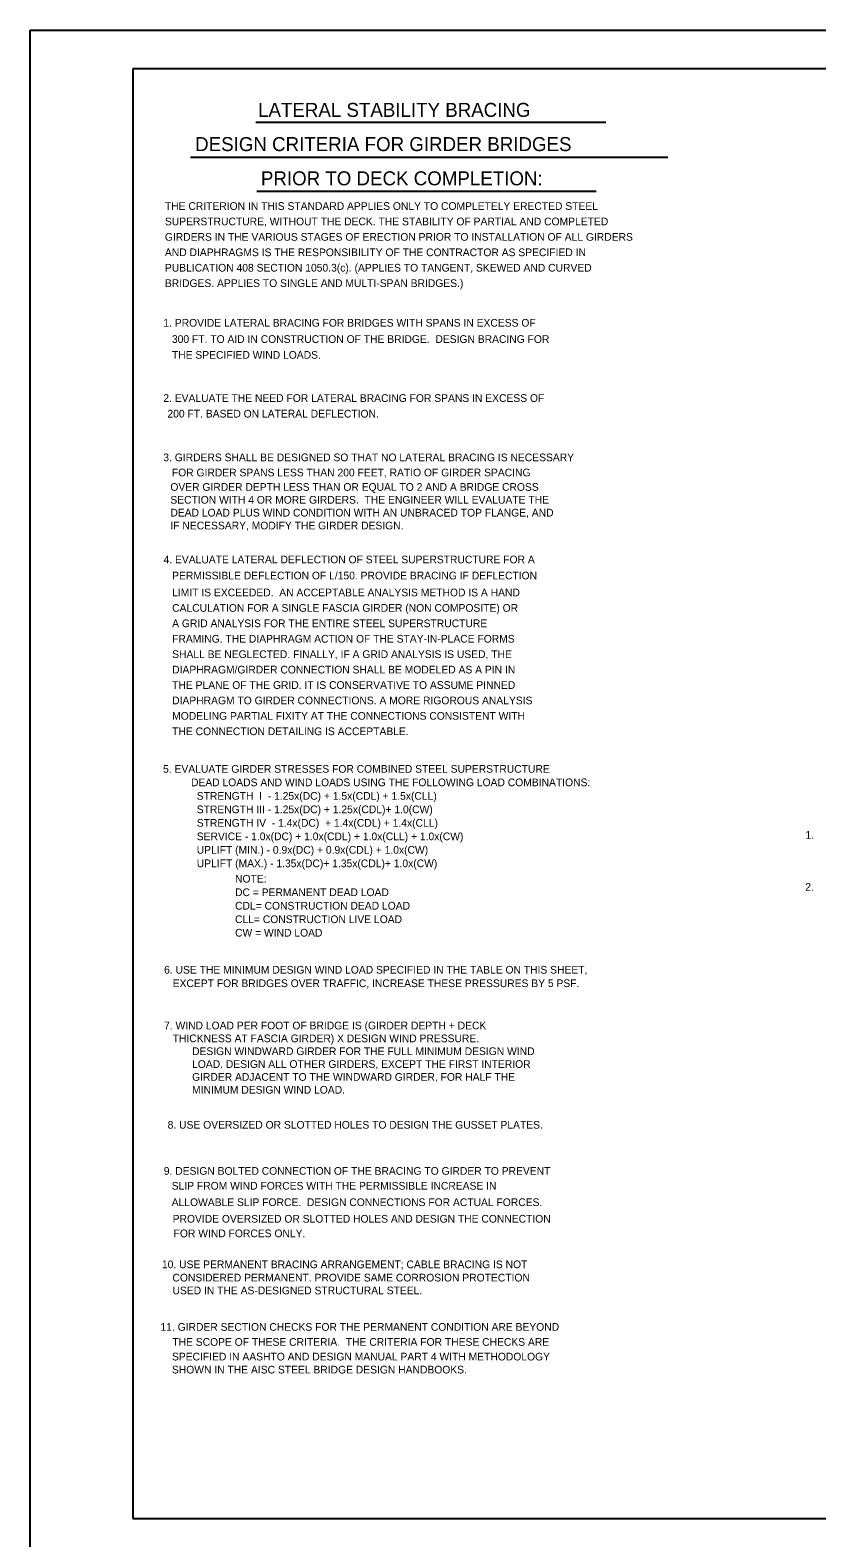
# Model space of a CAD drawing. Extents: x 30 to 2621, y -33 to 1155.
# Drawn here: x 30 to 337, y 568 to 1155 of the extents above; entities that cross this region are included whole.
import ezdxf

# ---------------------------------------------------------------- set-up
doc = ezdxf.new("R2010")
doc.units = 0
doc.layers.add('1', color=7, linetype='Continuous')
doc.layers.add('PLT-BNDY', color=7, linetype='Continuous')

msp = doc.modelspace()

# ---------------------------------------------------------------- linework, layer by layer
at = {"layer": '1'}
for p, q in [((856.5, 1140), (70.5, 1140)), ((70.5, 1140), (70.5, 576)), ((118.31, 1119.17), (254.54, 1119.17)), ((92.84, 1105.65), (278.69, 1105.65)), ((118.75, 1092.35), (250.78, 1092.35)), ((70.5, 576), (856.5, 576))]:
    msp.add_line(p, q, dxfattribs=at)
at = {"layer": 'PLT-BNDY'}
msp.add_lwpolyline([(30.5, 1155), (871.5, 1155), (871.5, 561), (30.5, 561)], close=True, dxfattribs=at)

# ---------------------------------------------------------------- texts
at = {"layer": '1'}
for s, height, p in [('LATERAL STABILITY BRACING', 5.445, (119.19, 1121.26)), ('DESIGN CRITERIA FOR GIRDER BRIDGES', 5.445, (94.71, 1107.95)), ('PRIOR TO DECK COMPLETION:', 5.445, (120.3, 1094.64)), ('THE CRITERION IN THIS STANDARD APPLIES ONLY TO COMPLETELY ERECTED STEEL', 3, (82.94, 1085.08)), ('SUPERSTRUCTURE, WITHOUT THE DECK. THE STABILITY OF PARTIAL AND COMPLETED', 3, (82.94, 1079.08)), ('GIRDERS IN THE VARIOUS STAGES OF ERECTION PRIOR TO INSTALLATION OF ALL GIRDERS', 3, (82.94, 1073.08)), ('AND DIAPHRAGMS IS THE RESPONSIBILITY OF THE CONTRACTOR AS SPECIFIED IN', 3, (82.94, 1067.08)), ('PUBLICATION 408 SECTION 1050.3(c). (APPLIES TO TANGENT, SKEWED AND CURVED', 3, (82.94, 1061.08)), ('BRIDGES. APPLIES TO SINGLE AND MULTI-SPAN BRIDGES.)', 3, (82.94, 1055.08)), (' 1. PROVIDE LATERAL BRACING FOR BRIDGES WITH SPANS IN EXCESS OF', 3, (81.21, 1039.65)), ('    300 FT. TO AID IN CONSTRUCTION OF THE BRIDGE.  DESIGN BRACING FOR', 3, (81.21, 1033.33)), ('    THE SPECIFIED WIND LOADS.', 3, (81.21, 1027.18)), (' 2. EVALUATE THE NEED FOR LATERAL BRACING FOR SPANS IN EXCESS OF', 3, (81.21, 1010.38)), ('     200 FT. BASED ON LATERAL DEFLECTION.', 3, (78.36, 1004.31)), (' 3. GIRDERS SHALL BE DESIGNED SO THAT NO LATERAL BRACING IS NECESSARY', 3, (81.21, 987.3)), ('    FOR GIRDER SPANS LESS THAN 200 FEET, RATIO OF GIRDER SPACING', 3, (81.21, 981.42)), ('    SECTION WITH 4 OR MORE GIRDERS.  THE ENGINEER WILL EVALUATE THE', 3, (80.61, 970.8)), ('    OVER GIRDER DEPTH LESS THAN OR EQUAL TO 2 AND A BRIDGE CROSS', 3, (80.61, 975.8)), ('    DEAD LOAD PLUS WIND CONDITION WITH AN UNBRACED TOP FLANGE, AND', 3, (80.61, 965.8)), ('    IF NECESSARY, MODIFY THE GIRDER DESIGN.', 3, (80.61, 960.8)), (' 4. EVALUATE LATERAL DEFLECTION OF STEEL SUPERSTRUCTURE FOR A', 3, (81.3, 947.59)), ('    PERMISSIBLE DEFLECTION OF L/150. PROVIDE BRACING IF DEFLECTION', 3, (81.3, 941.35)), ('    LIMIT IS EXCEEDED.  AN ACCEPTABLE ANALYSIS METHOD IS A HAND', 3, (81.3, 934.75)), ('    CALCULATION FOR A SINGLE FASCIA GIRDER (NON COMPOSITE) OR', 3, (81.3, 928.75)), ('    A GRID ANALYSIS FOR THE ENTIRE STEEL SUPERSTRUCTURE', 3, (81.3, 922.75)), ('    FRAMING. THE DIAPHRAGM ACTION OF THE STAY-IN-PLACE FORMS', 3, (81.3, 916.75)), ('    SHALL BE NEGLECTED. FINALLY, IF A GRID ANALYSIS IS USED, THE', 3, (81.3, 910.75)), ('    DIAPHRAGM/GIRDER CONNECTION SHALL BE MODELED AS A PIN IN', 3, (81.3, 904.75)), ('    THE PLANE OF THE GRID. IT IS CONSERVATIVE TO ASSUME PINNED', 3, (81.3, 898.75)), ('    DIAPHRAGM TO GIRDER CONNECTIONS. A MORE RIGOROUS ANALYSIS', 3, (81.3, 892.75)), ('    MODELING PARTIAL FIXITY AT THE CONNECTIONS CONSISTENT WITH', 3, (81.3, 886.75)), ('    THE CONNECTION DETAILING IS ACCEPTABLE.', 3, (81.3, 880.75)), (' 5. EVALUATE GIRDER STRESSES FOR COMBINED STEEL SUPERSTRUCTURE', 3, (81.12, 866.13)), ('DEAD LOADS AND WIND LOADS USING THE FOLLOWING LOAD COMBINATIONS:', 3, (93.1, 860.88)), ('  STRENGTH  I  - 1.25x(DC) + 1.5x(CDL) + 1.5x(CLL)', 3, (93.1, 855.63)), ('  STRENGTH III - 1.25x(DC) + 1.25x(CDL)+ 1.0(CW)', 3, (93.1, 850.38)), ('  STRENGTH IV  - 1.4x(DC)  + 1.4x(CDL) + 1.4x(CLL)', 3, (93.1, 845.13)), ('  SERVICE - 1.0x(DC) + 1.0x(CDL) + 1.0x(CLL) + 1.0x(CW)', 3, (93.1, 839.88)), ('1.', 3, (332.2, 840.46)), ('  UPLIFT (MIN.) - 0.9x(DC) + 0.9x(CDL) + 1.0x(CW)', 3, (93.1, 834.63)), ('  UPLIFT (MAX.) - 1.35x(DC)+ 1.35x(CDL)+ 1.0x(CW)', 3, (93.1, 829.38)), ('NOTE:', 3, (110.24, 823.39)), ('DC = PERMANENT DEAD LOAD', 3, (110.24, 818.14)), ('2.', 3, (332.12, 820.24)), ('CDL= CONSTRUCTION DEAD LOAD', 3, (110.24, 812.89)), ('CLL= CONSTRUCTION LIVE LOAD', 3, (110.24, 807.64)), ('CW = WIND LOAD', 3, (110.24, 802.39)), (' 6. USE THE MINIMUM DESIGN WIND LOAD SPECIFIED IN THE TABLE ON THIS SHEET,', 3, (81.51, 787.99)), ('    EXCEPT FOR BRIDGES OVER TRAFFIC, INCREASE THESE PRESSURES BY 5 PSF.', 3, (81.51, 782.74)), (' 7. WIND LOAD PER FOOT OF BRIDGE IS (GIRDER DEPTH + DECK', 3, (81.51, 766.3)), ('    THICKNESS AT FASCIA GIRDER) X DESIGN WIND PRESSURE.', 3, (81.51, 761.3)), ('DESIGN WINDWARD GIRDER FOR THE FULL MINIMUM DESIGN WIND', 3, (93.51, 756.3)), ('LOAD. DESIGN ALL OTHER GIRDERS, EXCEPT THE FIRST INTERIOR', 3, (93.51, 751.3)), ('GIRDER ADJACENT TO THE WINDWARD GIRDER, FOR HALF THE', 3, (93.51, 746.3)), ('MINIMUM DESIGN WIND LOAD.', 3, (93.51, 741.3)), ('8. USE OVERSIZED OR SLOTTED HOLES TO DESIGN THE GUSSET PLATES.', 3, (84.01, 727.67)), (' 9. DESIGN BOLTED CONNECTION OF THE BRACING TO GIRDER TO PREVENT', 3, (81.39, 709.74)), ('    SLIP FROM WIND FORCES WITH THE PERMISSIBLE INCREASE IN', 3, (81.13, 703.95)), ('    ALLOWABLE SLIP FORCE.  DESIGN CONNECTIONS FOR ACTUAL FORCES.', 3, (81.13, 697.56)), ('    PROVIDE OVERSIZED OR SLOTTED HOLES AND DESIGN THE CONNECTION', 3, (81.5, 691.12)), ('    FOR WIND FORCES ONLY.', 3, (81.88, 685.44)), ('10. USE PERMANENT BRACING ARRANGEMENT; CABLE BRACING IS NOT', 3, (81.78, 673.39)), ('    CONSIDERED PERMANENT. PROVIDE SAME CORROSION PROTECTION', 3, (81.43, 668.23)), ('    USED IN THE AS-DESIGNED STRUCTURAL STEEL.', 3, (81.43, 663.23)), ('11. GIRDER SECTION CHECKS FOR THE PERMANENT CONDITION ARE BEYOND ', 3, (81.22, 649.05)), ('    THE SCOPE OF THESE CRITERIA.  THE CRITERIA FOR THESE CHECKS ARE', 3, (81.35, 643.21)), ('    SPECIFIED IN AASHTO AND DESIGN MANUAL PART 4 WITH METHODOLOGY', 3, (81.22, 637.51)), ('    SHOWN IN THE AISC STEEL BRIDGE DESIGN HANDBOOKS.', 3, (81.22, 632.44))]:
    msp.add_text(s, height=height, dxfattribs=at).set_placement(p)

doc.saveas('drawing.dxf')
